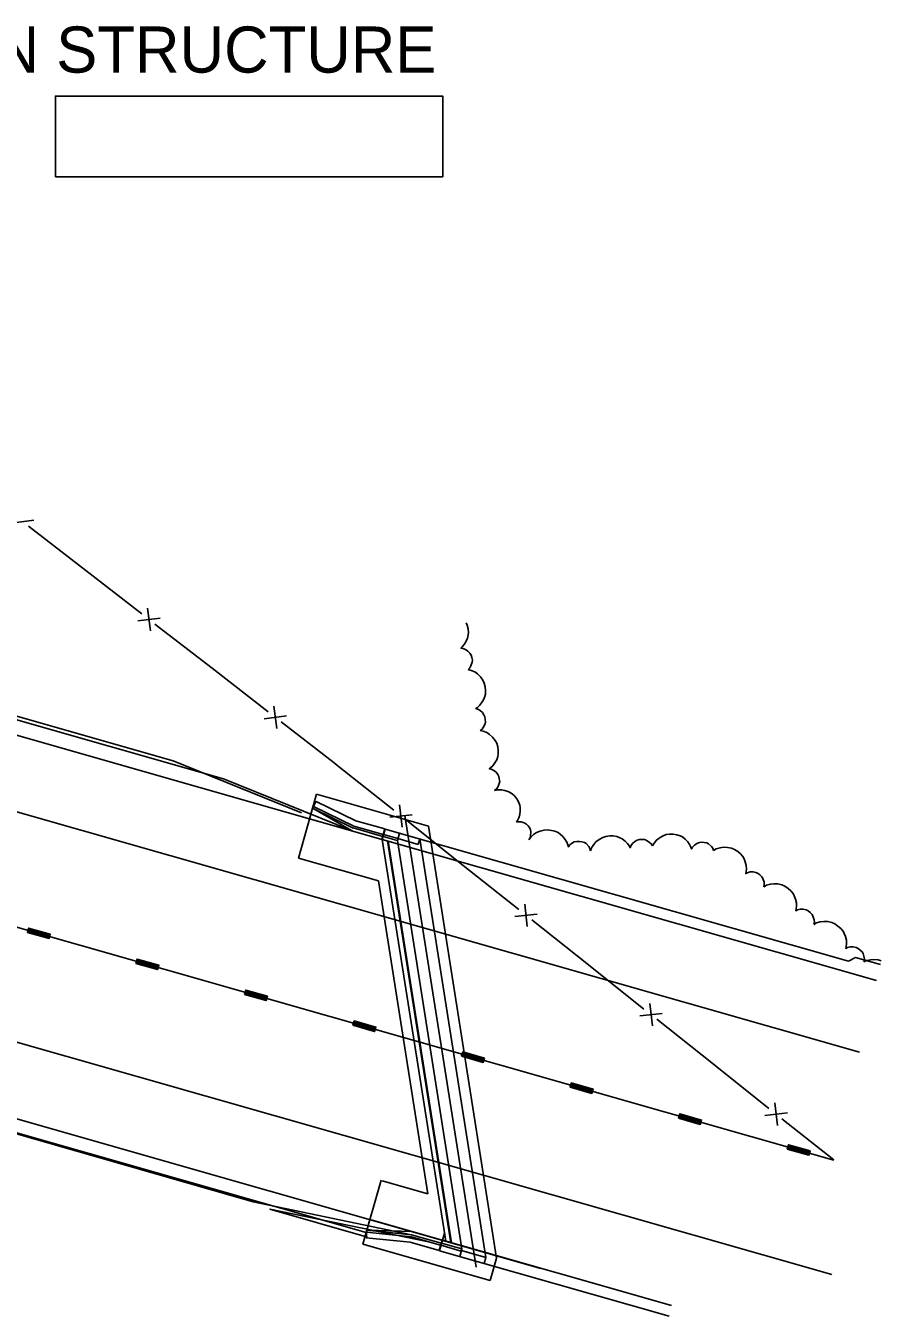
# Model space of a CAD drawing. Extents: x 3829340 to 3831660, y 499389 to 501171.
# Drawn here: x 3829898.3 to 3829954, y 499448 to 499531.9 of the extents above; entities that cross this region are included whole.
import ezdxf

# ---------------------------------------------------------------- set-up
doc = ezdxf.new("R2010")
doc.units = 0
for name, color, linetype in [('DIM TXT', 7, 'Continuous'), ('Level 20', 7, 'Continuous'), ('Level 21', 7, 'Continuous'), ('Level 26', 7, 'Continuous'), ('Level 27', 7, 'Continuous'), ('Level 48', 7, 'Continuous'), ('Level 50', 7, 'Continuous'), ('Level 51', 7, 'Continuous')]:
    doc.layers.add(name, color=color, linetype=linetype)

msp = doc.modelspace()

# ---------------------------------------------------------------- linework, layer by layer
at = {"layer": 'DIM TXT'}
msp.add_lwpolyline([(3829900.269, 499522.043), (3829925.461, 499522.043), (3829925.461, 499527.291), (3829900.269, 499527.292)], close=True, dxfattribs=at)
at = {"layer": 'Level 20'}
for points in [[(3829926.992, 499493.047), (3829927.051, 499492.893), (3829927.109, 499492.66), (3829927.134, 499492.43), (3829927.116, 499492.265), (3829927.066, 499492.046), (3829926.974, 499491.818), (3829926.859, 499491.633), (3829926.739, 499491.491), (3829926.647, 499491.401), (3829926.774, 499491.389), (3829926.944, 499491.321), (3829927.104, 499491.216), (3829927.226, 499491.076), (3829927.304, 499490.941), (3829927.356, 499490.789), (3829927.394, 499490.619), (3829927.384, 499490.492), (3829927.299, 499490.247), (3829927.234, 499490.122), (3829927.116, 499490.014)], [(3829927.115, 499490.015), (3829927.318, 499489.96), (3829927.551, 499489.855), (3829927.727, 499489.727), (3829927.92, 499489.537), (3829928.069, 499489.327), (3829928.161, 499489.124), (3829928.218, 499488.884), (3829928.245, 499488.65), (3829928.238, 499488.42), (3829928.198, 499488.261), (3829928.117, 499488.048), (3829927.995, 499487.839), (3829927.856, 499487.673), (3829927.717, 499487.544), (3829927.616, 499487.473), (3829927.738, 499487.439), (3829927.9, 499487.351), (3829928.042, 499487.226), (3829928.144, 499487.074), (3829928.205, 499486.931), (3829928.232, 499486.772), (3829928.245, 499486.6), (3829928.222, 499486.478), (3829928.103, 499486.244), (3829928.022, 499486.133), (3829927.893, 499486.041)], [(3829927.893, 499486.041), (3829928.096, 499486.001), (3829928.333, 499485.909), (3829928.516, 499485.787), (3829928.712, 499485.608), (3829928.875, 499485.408), (3829928.976, 499485.219), (3829929.041, 499484.982), (3829929.074, 499484.752), (3829929.078, 499484.525), (3829929.047, 499484.366), (3829928.976, 499484.153), (3829928.861, 499483.94), (3829928.733, 499483.763), (3829928.597, 499483.635), (3829928.496, 499483.557), (3829928.621, 499483.533), (3829928.787, 499483.452), (3829928.936, 499483.337), (3829929.044, 499483.192), (3829929.112, 499483.053), (3829929.145, 499482.904), (3829929.169, 499482.731), (3829929.145, 499482.606), (3829929.041, 499482.376), (3829928.963, 499482.257), (3829928.841, 499482.159)], [(3829928.841, 499482.159), (3829929.041, 499482.197), (3829929.294, 499482.2), (3829929.508, 499482.153), (3829929.755, 499482.061), (3829929.975, 499481.936), (3829930.134, 499481.794), (3829930.276, 499481.604), (3829930.388, 499481.408), (3829930.472, 499481.198), (3829930.499, 499481.039), (3829930.506, 499480.819), (3829930.476, 499480.582), (3829930.411, 499480.376), (3829930.337, 499480.21), (3829930.266, 499480.102), (3829930.391, 499480.122), (3829930.574, 499480.108), (3829930.753, 499480.058), (3829930.905, 499479.963), (3829931.014, 499479.861), (3829931.102, 499479.736), (3829931.176, 499479.584), (3829931.203, 499479.462), (3829931.183, 499479.212), (3829931.152, 499479.076), (3829931.071, 499478.944)], [(3829931.071, 499478.944), (3829931.19, 499479.11), (3829931.372, 499479.289), (3829931.558, 499479.411), (3829931.806, 499479.516), (3829932.063, 499479.58), (3829932.283, 499479.594), (3829932.53, 499479.56), (3829932.757, 499479.499), (3829932.973, 499479.415), (3829933.105, 499479.316), (3829933.278, 499479.168), (3829933.43, 499478.974), (3829933.535, 499478.785), (3829933.606, 499478.613), (3829933.637, 499478.487), (3829933.711, 499478.592), (3829933.85, 499478.707), (3829934.019, 499478.802), (3829934.202, 499478.842), (3829934.358, 499478.842), (3829934.516, 499478.812), (3829934.682, 499478.765), (3829934.787, 499478.697), (3829934.963, 499478.504), (3829935.041, 499478.386), (3829935.082, 499478.233)], [(3829935.082, 499478.233), (3829935.153, 499478.423), (3829935.285, 499478.643), (3829935.434, 499478.805), (3829935.644, 499478.971), (3829935.871, 499479.103), (3829936.08, 499479.168), (3829936.327, 499479.194), (3829936.558, 499479.194), (3829936.787, 499479.161), (3829936.943, 499479.103), (3829937.143, 499478.998), (3829937.336, 499478.853), (3829937.488, 499478.697), (3829937.593, 499478.545), (3829937.654, 499478.433), (3829937.701, 499478.552), (3829937.81, 499478.7), (3829937.952, 499478.829), (3829938.114, 499478.914), (3829938.263, 499478.954), (3829938.422, 499478.968), (3829938.591, 499478.961), (3829938.71, 499478.924), (3829938.926, 499478.778), (3829939.031, 499478.684), (3829939.106, 499478.545)], [(3829939.106, 499478.545), (3829939.211, 499478.724), (3829939.37, 499478.924), (3829939.539, 499479.059), (3829939.769, 499479.191), (3829940.01, 499479.283), (3829940.223, 499479.316), (3829940.466, 499479.309), (3829940.693, 499479.269), (3829940.913, 499479.208), (3829941.055, 499479.127), (3829941.235, 499478.992), (3829941.404, 499478.819), (3829941.526, 499478.64), (3829941.607, 499478.474), (3829941.651, 499478.355), (3829941.715, 499478.467), (3829941.837, 499478.599), (3829941.996, 499478.707), (3829942.169, 499478.765), (3829942.318, 499478.782), (3829942.477, 499478.768), (3829942.642, 499478.741), (3829942.754, 499478.68), (3829942.943, 499478.504), (3829943.032, 499478.399), (3829943.083, 499478.25)], [(3829943.083, 499478.25), (3829943.262, 499478.349), (3829943.505, 499478.433), (3829943.722, 499478.46), (3829943.99, 499478.453), (3829944.247, 499478.403), (3829944.45, 499478.321), (3829944.653, 499478.183), (3829944.832, 499478.03), (3829944.985, 499477.858), (3829945.066, 499477.716), (3829945.147, 499477.509), (3829945.205, 499477.272), (3829945.218, 499477.055), (3829945.205, 499476.869), (3829945.177, 499476.744), (3829945.289, 499476.805), (3829945.465, 499476.853), (3829945.655, 499476.863), (3829945.838, 499476.819), (3829945.976, 499476.758), (3829946.101, 499476.666), (3829946.23, 499476.548), (3829946.298, 499476.436), (3829946.369, 499476.189), (3829946.386, 499476.057), (3829946.358, 499475.898)], [(3829946.358, 499475.898), (3829946.538, 499475.993), (3829946.785, 499476.067), (3829947.005, 499476.088), (3829947.273, 499476.074), (3829947.53, 499476.02), (3829947.729, 499475.929), (3829947.936, 499475.786), (3829948.112, 499475.627), (3829948.264, 499475.455), (3829948.338, 499475.306), (3829948.423, 499475.093), (3829948.47, 499474.856), (3829948.481, 499474.639), (3829948.46, 499474.453), (3829948.433, 499474.328), (3829948.548, 499474.385), (3829948.728, 499474.426), (3829948.917, 499474.433), (3829949.1, 499474.382), (3829949.235, 499474.317), (3829949.364, 499474.219), (3829949.493, 499474.097), (3829949.553, 499473.989), (3829949.621, 499473.736), (3829949.642, 499473.6), (3829949.604, 499473.445)], [(3829949.604, 499473.445), (3829949.787, 499473.542), (3829950.03, 499473.617), (3829950.251, 499473.641), (3829950.521, 499473.624), (3829950.775, 499473.57), (3829950.975, 499473.482), (3829951.178, 499473.34), (3829951.361, 499473.184), (3829951.51, 499473.008), (3829951.591, 499472.862), (3829951.672, 499472.649), (3829951.723, 499472.412), (3829951.733, 499472.189), (3829951.716, 499472.006), (3829951.686, 499471.881), (3829951.801, 499471.945), (3829951.98, 499471.982), (3829952.173, 499471.986), (3829952.352, 499471.942), (3829952.491, 499471.877), (3829952.62, 499471.779), (3829952.742, 499471.657), (3829952.809, 499471.549), (3829952.877, 499471.299), (3829952.897, 499471.16), (3829952.86, 499471.004)], [(3829952.859, 499471.005), (3829953.047, 499471.09), (3829953.297, 499471.152), (3829953.519, 499471.164), (3829953.786, 499471.132), (3829953.991, 499471.077)]]:
    msp.add_lwpolyline(points, dxfattribs=at)
at = {"layer": 'Level 21'}
for p, q in [((3829897.413, 499499.535), (3829898.872, 499499.717)), ((3829906.264, 499493.995), (3829906.45, 499492.536)), ((3829905.631, 499493.175), (3829907.086, 499493.362)), ((3829913.845, 499486.809), (3829915.3, 499486.999)), ((3829914.481, 499487.635), (3829914.664, 499486.177)), ((3829922.661, 499481.222), (3829922.83, 499479.76)), ((3829922.018, 499480.406), (3829923.477, 499480.575)), ((3829930.8, 499474.761), (3829930.966, 499473.302)), ((3829930.154, 499473.949), (3829931.613, 499474.114)), ((3829938.287, 499467.491), (3829939.745, 499467.657)), ((3829938.933, 499468.304), (3829939.102, 499466.841)), ((3829947.07, 499461.843), (3829947.239, 499460.381)), ((3829946.423, 499461.027), (3829947.885, 499461.196))]:
    msp.add_line(p, q, dxfattribs=at)
for points in [[(3829898.523, 499499.332), (3829902.239, 499496.452)], [(3829902.239, 499496.452), (3829905.884, 499493.632)], [(3829906.741, 499492.969), (3829910.457, 499490.092)], [(3829910.457, 499490.092), (3829914.098, 499487.273)], [(3829914.951, 499486.61), (3829918.397, 499483.946), (3829918.667, 499483.73)], [(3829918.667, 499483.73), (3829922.275, 499480.863)], [(3829923.125, 499480.193), (3829926.803, 499477.269)], [(3829926.803, 499477.269), (3829930.411, 499474.406)], [(3829931.258, 499473.732), (3829934.94, 499470.808)], [(3829934.94, 499470.808), (3829938.547, 499467.945)], [(3829939.393, 499467.275), (3829943.076, 499464.35)], [(3829943.076, 499464.35), (3829946.683, 499461.487)], [(3829947.53, 499460.814), (3829950.901, 499458.138)]]:
    msp.add_lwpolyline(points, dxfattribs=at)
at = {"layer": 'Level 26'}
for p, q in [((3829836.105, 499503.308), (3829917.328, 499480.163)), ((3829835.509, 499498.489), (3829952.572, 499465.133)), ((3829833.722, 499484.034), (3829950.778, 499450.681)), ((3829833.126, 499479.216), (3829931.848, 499451.085))]:
    msp.add_line(p, q, dxfattribs=at)
at = {"layer": 'Level 27'}
for p, q in [((3829907.932, 499484.076), (3829877.253, 499492.818)), ((3829911.208, 499482.904), (3829880.444, 499491.67)), ((3829916.273, 499480.705), (3829907.934, 499484.076)), ((3829919.571, 499479.524), (3829911.21, 499482.904)), ((3829920.482, 499453.414), (3829862.387, 499469.967))]:
    msp.add_line(p, q, dxfattribs=at)
for points in [[(3829861.654, 499470.195), (3829913.134, 499455.409), (3829923.436, 499453.274)], [(3829920.573, 499453.117), (3829914.226, 499454.94), (3829924.528, 499452.805)]]:
    msp.add_lwpolyline(points, dxfattribs=at)
at = {"layer": 'Level 48'}
msp.add_line((3829834.616, 499491.262), (3829950.898, 499458.128), dxfattribs=at)
for points in [[(3829898.442, 499472.92), (3829899.857, 499472.521), (3829899.935, 499472.802), (3829898.523, 499473.204)], [(3829898.48, 499472.94), (3829899.833, 499472.558), (3829899.898, 499472.778), (3829898.544, 499473.164)], [(3829898.52, 499472.964), (3829899.809, 499472.595), (3829899.857, 499472.758), (3829898.567, 499473.123)], [(3829898.557, 499472.984), (3829899.793, 499472.632), (3829899.823, 499472.737), (3829898.584, 499473.093)], [(3829898.584, 499473.001), (3829899.776, 499472.66), (3829899.796, 499472.723), (3829898.601, 499473.062)], [(3829898.608, 499473.015), (3829899.762, 499472.686), (3829899.769, 499472.71), (3829898.615, 499473.038)], [(3829905.502, 499470.91), (3829906.913, 499470.507), (3829906.998, 499470.788), (3829905.584, 499471.19)], [(3829905.543, 499470.93), (3829906.893, 499470.544), (3829906.957, 499470.767), (3829905.604, 499471.153)], [(3829905.584, 499470.954), (3829906.869, 499470.585), (3829906.917, 499470.747), (3829905.627, 499471.113)], [(3829905.614, 499470.974), (3829906.853, 499470.619), (3829906.883, 499470.727), (3829905.647, 499471.079)], [(3829905.644, 499470.991), (3829906.839, 499470.649), (3829906.856, 499470.71), (3829905.665, 499471.052)], [(3829905.668, 499471.004), (3829906.825, 499470.676), (3829906.829, 499470.696), (3829905.675, 499471.025)], [(3829912.569, 499468.899), (3829913.976, 499468.493), (3829914.058, 499468.778), (3829912.647, 499469.18)], [(3829912.603, 499468.92), (3829913.956, 499468.534), (3829914.017, 499468.757), (3829912.667, 499469.14)], [(3829912.643, 499468.943), (3829913.933, 499468.574), (3829913.976, 499468.734), (3829912.691, 499469.102)], [(3829912.677, 499468.96), (3829913.916, 499468.608), (3829913.946, 499468.717), (3829912.711, 499469.069)], [(3829912.708, 499468.974), (3829913.899, 499468.635), (3829913.916, 499468.7), (3829912.724, 499469.041)], [(3829912.731, 499468.991), (3829913.885, 499468.659), (3829913.892, 499468.686), (3829912.738, 499469.014)], [(3829919.625, 499466.885), (3829921.036, 499466.483), (3829921.121, 499466.767), (3829919.706, 499467.17)], [(3829919.666, 499466.906), (3829921.016, 499466.523), (3829921.081, 499466.743), (3829919.727, 499467.129)], [(3829919.706, 499466.93), (3829920.996, 499466.564), (3829921.04, 499466.723), (3829919.75, 499467.088)], [(3829919.737, 499466.95), (3829920.976, 499466.598), (3829921.003, 499466.703), (3829919.767, 499467.051)], [(3829919.764, 499466.963), (3829920.962, 499466.625), (3829920.979, 499466.686), (3829919.784, 499467.028)], [(3829919.791, 499466.977), (3829920.945, 499466.649), (3829920.955, 499466.675), (3829919.798, 499467.004)], [(3829926.688, 499464.872), (3829928.103, 499464.473), (3829928.181, 499464.753), (3829926.77, 499465.156)], [(3829926.726, 499464.896), (3829928.08, 499464.51), (3829928.14, 499464.733), (3829926.79, 499465.119)], [(3829926.766, 499464.919), (3829928.056, 499464.55), (3829928.103, 499464.709), (3829926.81, 499465.078)], [(3829926.803, 499464.936), (3829928.036, 499464.584), (3829928.069, 499464.689), (3829926.831, 499465.041)], [(3829926.831, 499464.953), (3829928.022, 499464.614), (3829928.042, 499464.675), (3829926.848, 499465.014)], [(3829926.851, 499464.967), (3829928.009, 499464.635), (3829928.015, 499464.662), (3829926.861, 499464.99)], [(3829933.748, 499462.861), (3829935.159, 499462.459), (3829935.241, 499462.743), (3829933.83, 499463.146)], [(3829933.789, 499462.885), (3829935.136, 499462.496), (3829935.203, 499462.719), (3829933.85, 499463.105)], [(3829933.83, 499462.905), (3829935.115, 499462.536), (3829935.163, 499462.699), (3829933.874, 499463.065)], [(3829933.86, 499462.922), (3829935.099, 499462.574), (3829935.129, 499462.679), (3829933.89, 499463.03)], [(3829933.89, 499462.939), (3829935.085, 499462.601), (3829935.102, 499462.662), (3829933.907, 499463.004)], [(3829933.914, 499462.953), (3829935.068, 499462.624), (3829935.075, 499462.648), (3829933.921, 499462.98)], [(3829940.812, 499460.851), (3829942.223, 499460.445), (3829942.304, 499460.729), (3829940.889, 499461.136)], [(3829940.849, 499460.871), (3829942.203, 499460.485), (3829942.263, 499460.709), (3829940.913, 499461.095)], [(3829940.889, 499460.892), (3829942.179, 499460.526), (3829942.223, 499460.688), (3829940.937, 499461.054)], [(3829940.923, 499460.912), (3829942.159, 499460.56), (3829942.189, 499460.668), (3829940.957, 499461.017)], [(3829940.954, 499460.929), (3829942.142, 499460.587), (3829942.162, 499460.651), (3829940.97, 499460.993)], [(3829940.977, 499460.939), (3829942.131, 499460.614), (3829942.135, 499460.638), (3829940.981, 499460.966)], [(3829947.872, 499458.837), (3829949.283, 499458.435), (3829949.364, 499458.719), (3829947.953, 499459.118)], [(3829947.909, 499458.861), (3829949.263, 499458.475), (3829949.327, 499458.695), (3829947.97, 499459.084)], [(3829947.949, 499458.881), (3829949.239, 499458.516), (3829949.283, 499458.671), (3829947.993, 499459.044)], [(3829947.983, 499458.902), (3829949.222, 499458.546), (3829949.249, 499458.655), (3829948.014, 499459.006)], [(3829948.01, 499458.915), (3829949.208, 499458.577), (3829949.225, 499458.638), (3829948.03, 499458.979)], [(3829948.037, 499458.929), (3829949.192, 499458.6), (3829949.201, 499458.624), (3829948.044, 499458.952)]]:
    msp.add_lwpolyline(points, close=True, dxfattribs=at)
at = {"layer": 'Level 50'}
msp.add_line((3829923.006, 499480.528), (3829927.646, 499451.161), dxfattribs=at)
at = {"layer": 'Level 51'}
for p, q in [((3829916.078, 499477.76), (3829917.259, 499481.912)), ((3829917.259, 499481.912), (3829924.529, 499479.838)), ((3829917.002, 499480.995), (3829917.222, 499481.448)), ((3829917.061, 499481.115), (3829919.686, 499479.839)), ((3829917.221, 499481.445), (3829919.814, 499480.186)), ((3829916.806, 499480.312), (3829917.002, 499480.995)), ((3829916.891, 499480.288), (3829921.505, 499478.972)), ((3829917.001, 499480.993), (3829919.636, 499479.711)), ((3829919.571, 499479.523), (3829917.002, 499480.995)), ((3829919.635, 499479.712), (3829921.561, 499479.164)), ((3829919.686, 499479.838), (3829921.595, 499479.293)), ((3829919.814, 499480.186), (3829921.698, 499479.649)), ((3829921.696, 499479.648), (3829921.504, 499478.971)), ((3829921.723, 499479.641), (3829921.53, 499478.965)), ((3829921.723, 499479.641), (3829951.872, 499471.052)), ((3829922.648, 499479.377), (3829922.512, 499478.893)), ((3829924.529, 499479.838), (3829928.969, 499451.744)), ((3829921.53, 499478.967), (3829953.686, 499469.803)), ((3829921.53, 499478.965), (3829925.656, 499452.85)), ((3829921.585, 499479.157), (3829922.509, 499478.893)), ((3829921.619, 499479.289), (3829922.546, 499479.025)), ((3829921.869, 499478.87), (3829925.995, 499452.752)), ((3829921.909, 499478.86), (3829926.039, 499452.742)), ((3829922.512, 499478.893), (3829926.709, 499452.346)), ((3829922.546, 499479.025), (3829923.873, 499478.646)), ((3829923.978, 499478.998), (3829923.873, 499478.643)), ((3829923.978, 499478.998), (3829928.276, 499451.788)), ((3829916.078, 499477.76), (3829921.29, 499476.27)), ((3829921.29, 499476.27), (3829924.502, 499455.94)), ((3829951.872, 499471.052), (3829952.317, 499471.299)), ((3829952.317, 499471.299), (3829953.934, 499470.837)), ((3829921.449, 499456.81), (3829920.262, 499452.658)), ((3829921.53, 499456.786), (3829924.506, 499455.94)), ((3829920.526, 499453.578), (3829920.722, 499454.258)), ((3829920.803, 499454.233), (3829925.418, 499452.919)), ((3829920.526, 499453.576), (3829920.473, 499453.074)), ((3829920.511, 499453.441), (3829923.409, 499453.141)), ((3829920.526, 499453.576), (3829923.436, 499453.274)), ((3829923.473, 499453.473), (3829920.546, 499453.575)), ((3829925.25, 499452.238), (3829925.575, 499453.378)), ((3829920.262, 499452.658), (3829928.56, 499450.295)), ((3829920.473, 499453.074), (3829923.341, 499452.779)), ((3829923.341, 499452.779), (3829925.225, 499452.242)), ((3829923.409, 499453.141), (3829925.325, 499452.593)), ((3829923.436, 499453.274), (3829925.362, 499452.725)), ((3829925.226, 499452.241), (3829925.419, 499452.918)), ((3829925.348, 499452.59), (3829926.672, 499452.214)), ((3829925.385, 499452.718), (3829926.709, 499452.346)), ((3829925.44, 499452.912), (3829940.35, 499448.662)), ((3829925.248, 499452.234), (3829940.188, 499447.977)), ((3829926.57, 499451.859), (3829926.709, 499452.346)), ((3829926.678, 499452.241), (3829928.276, 499451.788)), ((3829928.164, 499451.405), (3829928.276, 499451.788)), ((3829928.56, 499450.295), (3829928.969, 499451.747))]:
    msp.add_line(p, q, dxfattribs=at)

# ---------------------------------------------------------------- texts
at = {"layer": 'DIM TXT'}
msp.add_text('SIGN STRUCTURE', height=3.00008, dxfattribs=at).set_placement((3829889.396, 499528.813))

doc.saveas('drawing.dxf')
